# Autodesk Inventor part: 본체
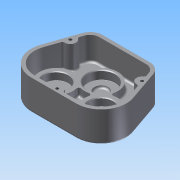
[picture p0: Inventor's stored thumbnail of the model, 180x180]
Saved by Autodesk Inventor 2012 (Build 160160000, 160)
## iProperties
Created: 2014-12
Part Number: 본체
Material: Default
Document SubType Name: Modeling
Designer: Owner
Density: 1 g/cm^3
Author: Owner
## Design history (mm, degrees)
sketch "스케치1"
  geometry: L1 (0, 0)-(-42.388, -42.388); L2 (0, 0)-(24.229, -24.229); L3 (-47, 36)-(47, 36); L4 (-47, 36)-(-66.565, -20.803); L5 (47, 36)-(66.565, -20.803); L6 (-32.527, -68.527)-(32.527, -68.527); A1 r 46 centre (0, 0) between (32.527, -32.527) and (-32.527, -32.527); A2 r 36 centre (-32.527, -32.527) between (-66.565, -20.803) and (-32.527, -68.527); A3 r 36 centre (32.527, -32.527) between (32.527, -68.527) and (66.565, -20.803); 3 further points
  constraints: 12 end point, 6 point on circle, 3 centre point, 3 tangent, 2 coincident, 2 midpoint, 2 point on line, 2 vertical alignment, 1 horizontal, 1 parallel
  dimensions: "d0" = 92 diameter of A1; "d1" = 90 deg angle of L2 L1; "d2" = 94 distance of L3.start L3.end; "d3" = 36 distance from line of L1.start L3; "d6" = 36 radius of A2; "d7" = 36 radius of A3
extrude "돌출1" new body sketch "스케치1" distance "d8" = 44; taper "d9" = 0 deg
sketch "스케치2"
  geometry: C1 r 20 at (-32.527, -32.527); C2 r 20 at (32.527, -32.527); A1 r 36 centre (-32.527, -32.527) between (-66.565, -20.803) and (-32.527, -68.527) reference; A2 r 36 centre (32.527, -32.527) between (32.527, -68.527) and (66.565, -20.803) reference; 1 further point
  constraints: 2 centre point, 2 coincident
  dimensions: "d10" = 40 diameter of C1; "d11" = 40 diameter of C2
extrude "돌출2" join sketch "스케치2" distance "d12" = 7; taper "d13" = 0 deg
chamfer "모따기1" distance "d14" = 7; stored, may be unused: second distance "d15" = 2, angle "d16" = 10 deg
sketch "스케치3"
  geometry: L1 (0, -44)-(94, -44) reference; L2 (94, 0)-(94, -44) reference; L3 (0, 0)-(94, 0) reference; L4 (0, 0)-(0, -44) reference; L5 (0, -44)-(0, 0) reference; L6 (0, 0)-(94, 0) reference; L7 (94, 0)-(94, -44) reference; L8 (94, -44)-(0, -44) reference; L9 (60.761, 7)-(59.527, 0) reference; L10 (79.527, 0)-(14.473, 0) reference; 1 further point
  node "절단 모서리 투영1"
chamfer "모따기2" distance "d17" = 7; stored, may be unused: second distance "d18" = 2, angle "d19" = 10 deg
fillet "모깎기1" dims "d20" = 18
hole "구멍1" diameter "d23" = 15.5; stored, may be unused: countersink angle "d27" = 90 deg, drill point angle "d29" = 118 deg; dims "d21" = 10, "d22" = 10, "d24" = 6, "d25" = 4, "d26" = 2, "d28" = 8
hole "구멍2" diameter "d32" = 15.5; stored, may be unused: countersink angle "d36" = 90 deg, drill point angle "d38" = 118 deg; dims "d30" = 10, "d31" = 10, "d33" = 6, "d34" = 4, "d35" = 2, "d37" = 8
hole "구멍3" diameter "d41" = 30; stored, may be unused: countersink angle "d45" = 90 deg, drill point angle "d47" = 0 deg; dims "d39" = 10, "d40" = 10, "d42" = 6, "d43" = 4, "d44" = 2, "d46" = 7
hole "구멍4" diameter "d50" = 30; stored, may be unused: countersink angle "d54" = 90 deg, drill point angle "d56" = 0 deg; dims "d48" = 10, "d49" = 10, "d51" = 6, "d52" = 4, "d53" = 2, "d55" = 7
chamfer "모따기3" distance "d57" = 1; stored, may be unused: second distance "d58" = 2, angle "d59" = 45 deg
fillet "모깎기2" dims "d60" = 3
fillet "모깎기3" dims "d61" = 3
node "작업 평면1"
sketch "스케치4"
  geometry: L1 (34.162, 36)-(-34.162, 36) reference; 2 further points
  constraints: 1 vertical alignment, 1 other
  dimensions: "d63" = 30 distance from line of point (0, 6) L1
feature "엠보싱1" sketch "스케치4" dims "d0" = 92, "d1" = 90 deg, "d2" = 94, "d3" = 36, "d6" = 36, "d7" = 36, "d64" = 1, "d65" = 0
sketch "스케치5"
  geometry: C1 r 20 at (0, 0); 1 further point
  constraints: 1 centre point, 1 coincident
  dimensions: "d66" = 40 diameter of C1
extrude "돌출3" cut sketch "스케치5" distance "d67" = 35; taper "d68" = 0 deg
hole "구멍5" diameter "d71" = 20; stored, may be unused: countersink angle "d75" = 90 deg, drill point angle "d77" = 0 deg; dims "d69" = 10, "d70" = 10, "d72" = 6, "d73" = 4, "d74" = 2, "d76" = 3
fillet "모깎기4" dims "d78" = 0.3
fillet "모깎기5" dims "d79" = 3
sketch "스케치8"
  geometry: L1 (-66.565, -20.803)-(-51.181, 23.862) reference; L2 (51.181, 23.862)-(66.565, -20.803) reference; L3 (-34.162, 31)-(34.162, 31); L4 (-32.527, -63.527)-(32.527, -63.527); L5 (-46.453, 22.233)-(-61.837, -22.432); L6 (46.453, 22.233)-(61.837, -22.432); C1 r 7.75 at (-32.527, -32.527) reference; C2 r 7.75 at (32.527, -32.527) reference; A1 r 36 centre (-32.527, -32.527) between (-66.565, -20.803) and (-32.527, -68.527) reference; A2 r 36 centre (32.527, -32.527) between (32.527, -68.527) and (66.565, -20.803) reference; A3 r 18 centre (34.162, 18) between (51.181, 23.862) and (34.162, 36) reference; A4 r 13 centre (-34.162, 18) between (-34.162, 31) and (-46.453, 22.233); A5 r 13 centre (34.162, 18) between (46.453, 22.233) and (34.162, 31); A6 r 31 centre (-32.527, -32.527) between (-61.837, -22.432) and (-32.527, -63.527); A7 r 31 centre (32.527, -32.527) between (32.527, -63.527) and (61.837, -22.432); 2 further points
  constraints: 8 end point, 8 point on circle, 5 tangent, 4 centre point, 3 coincident, 3 parallel, 1 midpoint, 1 vertical alignment
  dimensions: "d83" = 5 radial gap between concentric circles of A6 A1
extrude "돌출4" cut sketch "스케치8" distance "d84" = 23; taper "d85" = 0 deg
hole "구멍6" diameter "d88" = 35; stored, may be unused: countersink angle "d92" = 90 deg, drill point angle "d94" = 0 deg; dims "d86" = 10, "d87" = 10, "d89" = 6, "d90" = 4, "d91" = 2, "d93" = 11
hole "구멍7" diameter "d97" = 35; stored, may be unused: countersink angle "d101" = 90 deg, drill point angle "d103" = 0 deg; dims "d95" = 10, "d96" = 10, "d98" = 6, "d99" = 4, "d100" = 2, "d102" = 11
sketch "스케치9"
  geometry: L1 (-61.837, -22.432)-(-46.453, 22.233) reference; L2 (-34.162, 31)-(34.162, 31) reference; L3 (46.453, 22.233)-(61.837, -22.432) reference; L4 (32.527, -63.527)-(-32.527, -63.527) reference; C1 r 20 at (0, 0) reference; C2 r 24 at (32.527, -32.527); C3 r 24 at (-32.527, -32.527); C4 r 24 at (0, 0); A1 r 13 centre (-34.162, 18) between (-34.162, 31) and (-46.453, 22.233) reference; A2 r 31 centre (-32.527, -32.527) between (-61.837, -22.432) and (-32.527, -63.527) reference; A3 r 31 centre (32.527, -32.527) between (32.527, -63.527) and (61.837, -22.432) reference; A4 r 13 centre (-34.162, 18) between (-34.162, 31) and (-46.453, 22.233) reference; A5 r 13 centre (34.162, 18) between (46.453, 22.233) and (34.162, 31) reference; A6 r 31 centre (32.527, -32.527) between (32.527, -63.527) and (61.837, -22.432) reference
  constraints: 3 centre point, 3 coincident
  dimensions: "d104" = 48 diameter of C2; "d105" = 48 diameter of C3; "d106" = 48 diameter of C4
extrude "돌출5" cut sketch "스케치9" distance "d107" = 11; taper "d108" = 0 deg
fillet "모깎기6" dims "d109" = 3
chamfer "모따기4" distance "d110" = 1; stored, may be unused: second distance "d111" = 2, angle "d112" = 45 deg
fillet "모깎기7" dims "d113" = 3
fillet "모깎기8" dims "d114" = 3
fillet "모깎기9" dims "d115" = 3
sketch "스케치10"
  geometry: L1 (46.453, 22.233)-(61.837, -22.432) reference; L2 (32.527, -63.527)-(-32.527, -63.527) reference; L3 (-61.837, -22.432)-(-46.453, 22.233) reference; L4 (51.181, 23.862)-(66.565, -20.803) reference; L5 (-34.162, 36)-(34.162, 36) reference; L6 (-49.095, 14.564)-(-54.305, -0.564); L7 (49.095, 14.564)-(54.305, -0.564); L8 (-8, -63.527)-(8, -63.527); A1 r 8 centre (51.7, 7) between (49.095, 14.564) and (54.305, -0.564); A2 r 8 centre (-51.7, 7) between (-54.305, -0.564) and (-49.095, 14.564); A3 r 8 centre (0, -63.527) between (8, -63.527) and (-8, -63.527); 1 further point
  constraints: 8 point on line, 6 end point, 6 point on circle, 3 centre point, 2 parallel, 1 collinear, 1 midpoint
  dimensions: "d116" = 29 distance from line of A1.centre L5; "d117" = 29 distance from line of A2.centre L5; "d121" = 8 radius of A3; "d122" = 8 radius of A1; "d123" = 8 radius of A2
extrude "돌출6" join sketch "스케치10" stored distance "d124" = 11; taper "d125" = 0 deg
fillet "모깎기10" dims "d126" = 3
sketch "스케치11"
  geometry: A1 r 8 centre (51.7, 7) between (47.131, 13.567) and (52.144, -0.988) reference; A2 r 8 centre (0, -63.527) between (7.697, -61.345) and (-7.697, -61.345) reference; A3 r 8 centre (-51.7, 7) between (-52.144, -0.988) and (-47.131, 13.567) reference; 4 further points
  constraints: 3 coincident
hole "구멍8" sketch "스케치11" at (-51.7, 7), (0, -63.527), (51.7, 7) diameter "d127" = 4.134; stored, may be unused: countersink angle "d131" = 90 deg, drill point angle "d133" = 118 deg; dims "d128" = 20, "d129" = 4, "d130" = 2, "d132" = 23
fillet "모깎기11" dims "d137" = 0.3
chamfer "모따기6" distance "d138" = 1; stored, may be unused: second distance "d139" = 2, angle "d140" = 45 deg
fillet "모깎기12" dims "d141" = 0.1
node "솔리드1"
other parameters: "d4" = 72, "d5" = 72, "d62" = 26.25, "d81" = 5, "d82" = 5, "d118" = 16, "d119" = 16, "d120" = 16
